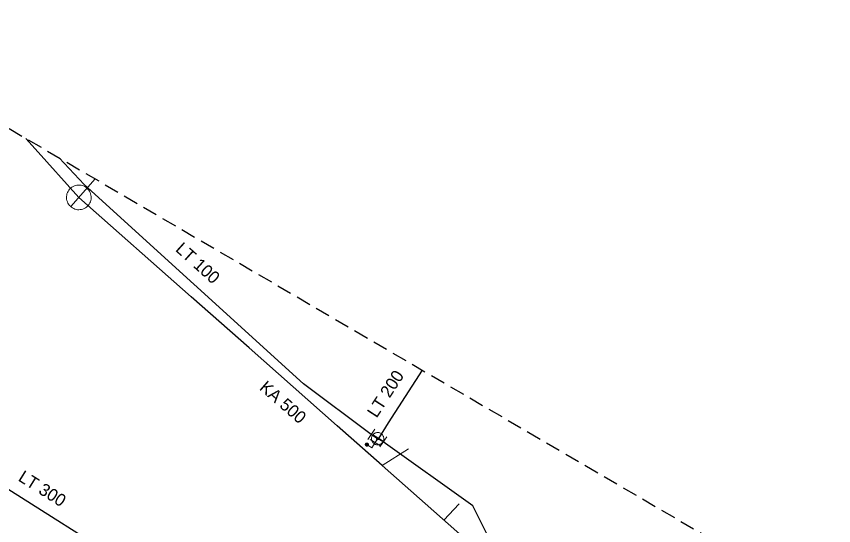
# Model space of a CAD drawing. Extents: x -747112 to -746911, y -964685 to -964545.
# Drawn here: x -747078.9 to -747012.7, y -964586.1 to -964544.9 of the extents above; entities that cross this region are included whole.
import ezdxf

# ---------------------------------------------------------------- set-up
doc = ezdxf.new("R2010")
doc.units = 0
doc.header["$LTSCALE"] = 0.4
doc.linetypes.add('MEDIUM_DASHED', pattern=[4.5, 3, -1.5])
doc.layers.add('1', color=7, linetype='Continuous')
for name, color, linetype, lineweight in [('11', 7, 'Continuous', 13), ('14', 7, 'Continuous', 13), ('17', 7, 'Continuous', 25), ('22', 7, 'Continuous', 13), ('34', 7, 'Continuous', 13), ('47', 7, 'Continuous', 13), ('63', 7, 'MEDIUM_DASHED', 25), ('9', 7, 'Continuous', 13)]:
    doc.layers.add(name, color=color, linetype=linetype, lineweight=lineweight)

msp = doc.modelspace()

# ---------------------------------------------------------------- linework, layer by layer
at = {"layer": '11'}
for p, q in [((-747047.181, -964579.934), (-747049.3, -964581.28)), ((-747043.061, -964584.386), (-747044.313, -964585.69))]:
    msp.add_line(p, q, dxfattribs=at)
at = {"layer": '14'}
for p, q in [((-747049.67, -964579.109), (-747050.182, -964578.759)), ((-747049.67, -964579.109), (-747049.857, -964579.421)), ((-747049.579, -964579.079), (-747049.67, -964579.109)), ((-747049.208, -964579.357), (-747049.67, -964579.109))]:
    msp.add_line(p, q, dxfattribs=at)
at = {"layer": '14', "lineweight": 25}
for points in [[(-747073.861, -964559.579), (-747077.397, -964555.642), (-747078.147, -964554.806)], [(-747037.631, -964591.6), (-747040.938, -964588.675), (-747049.3, -964581.28), (-747052.956, -964578.054), (-747060.077, -964571.761), (-747064.767, -964567.616), (-747073.861, -964559.579)]]:
    msp.add_lwpolyline(points, dxfattribs=at)
at = {"layer": '14'}
msp.add_lwpolyline([(-747049.857, -964579.421), (-747050.124, -964579.837), (-747050.539, -964579.583)], dxfattribs=at)
at = {"layer": '17'}
for points in [[(-747050.182, -964578.759), (-747055.68, -964574.68), (-747073.416, -964558.543), (-747075.451, -964556.382)], [(-747106.776, -964565.501), (-747102.855, -964568.884), (-747090.37, -964576.361), (-747069.903, -964589.309), (-747064.75, -964592.568), (-747063.288, -964593.435)], [(-747049.579, -964579.079), (-747048.793, -964577.816), (-747046.042, -964573.57)], [(-746992.592, -964623.377), (-747002.848, -964615.868), (-747011.265, -964609.743), (-747020.612, -964602.861), (-747030.192, -964595.879), (-747034.92, -964592.421), (-747039.8, -964588.87), (-747041.949, -964584.539), (-747049.208, -964579.357)]]:
    msp.add_lwpolyline(points, dxfattribs=at)
at = {"layer": '22'}
msp.add_line((-747072.536, -964558.079), (-747074.522, -964560.327), dxfattribs=at)
msp.add_lwpolyline([(-747074.609, -964558.916), (-747074.677, -964559.002), (-747074.735, -964559.094), (-747074.783, -964559.194), (-747074.82, -964559.296), (-747074.845, -964559.403), (-747074.858, -964559.511), (-747074.859, -964559.621), (-747074.848, -964559.73), (-747074.826, -964559.838), (-747074.792, -964559.941), (-747074.747, -964560.041), (-747074.69, -964560.135), (-747074.624, -964560.223), (-747074.549, -964560.302), (-747074.466, -964560.374), (-747074.376, -964560.435), (-747074.279, -964560.487), (-747074.177, -964560.527), (-747074.071, -964560.555), (-747073.964, -964560.573), (-747073.854, -964560.578), (-747073.745, -964560.571), (-747073.636, -964560.553), (-747073.531, -964560.523), (-747073.43, -964560.481), (-747073.334, -964560.428), (-747073.244, -964560.365), (-747073.162, -964560.294), (-747073.088, -964560.213), (-747073.023, -964560.124), (-747072.968, -964560.03), (-747072.925, -964559.93), (-747072.891, -964559.826), (-747072.87, -964559.718), (-747072.861, -964559.609), (-747072.863, -964559.5), (-747072.878, -964559.391), (-747072.904, -964559.285), (-747072.942, -964559.182), (-747072.991, -964559.084), (-747073.05, -964558.992), (-747073.119, -964558.907), (-747073.197, -964558.829), (-747073.283, -964558.762), (-747073.376, -964558.704), (-747073.474, -964558.656), (-747073.577, -964558.619), (-747073.684, -964558.594), (-747073.793, -964558.581), (-747073.902, -964558.579), (-747074.011, -964558.589), (-747074.118, -964558.612), (-747074.222, -964558.645), (-747074.322, -964558.691), (-747074.416, -964558.747), (-747074.504, -964558.813), (-747074.584, -964558.888)], close=True, dxfattribs=at)
at = {"layer": '34'}
for p, q in [((-747050.464, -964579.171), (-747049.899, -964578.346)), ((-747050.006, -964578.819), (-747049.152, -964579.339)), ((-747049.428, -964579.679), (-747050.284, -964579.161)), ((-747049.498, -964579.764), (-747048.917, -964578.95))]:
    msp.add_line(p, q, dxfattribs=at)
at = {"layer": '47'}
for points in [[(-747050.11, -964578.872), (-747050.132, -964578.919), (-747050.149, -964578.968), (-747050.161, -964579.019), (-747050.168, -964579.071), (-747050.169, -964579.124), (-747050.165, -964579.176), (-747050.154, -964579.227), (-747050.139, -964579.277), (-747050.12, -964579.325), (-747050.095, -964579.371), (-747050.065, -964579.415), (-747050.03, -964579.454), (-747049.993, -964579.49), (-747049.951, -964579.522), (-747049.906, -964579.549), (-747049.859, -964579.571), (-747049.81, -964579.588), (-747049.758, -964579.6), (-747049.707, -964579.607), (-747049.654, -964579.608), (-747049.602, -964579.604), (-747049.55, -964579.594), (-747049.5, -964579.579), (-747049.452, -964579.559), (-747049.407, -964579.534), (-747049.363, -964579.504), (-747049.323, -964579.47), (-747049.288, -964579.432), (-747049.256, -964579.39), (-747049.229, -964579.345), (-747049.207, -964579.298), (-747049.19, -964579.249), (-747049.177, -964579.198), (-747049.171, -964579.146), (-747049.17, -964579.093), (-747049.174, -964579.041), (-747049.183, -964578.99), (-747049.198, -964578.94), (-747049.219, -964578.891), (-747049.244, -964578.846), (-747049.274, -964578.802), (-747049.307, -964578.763), (-747049.346, -964578.727), (-747049.388, -964578.695), (-747049.433, -964578.668), (-747049.48, -964578.646), (-747049.529, -964578.629), (-747049.58, -964578.616), (-747049.632, -964578.61), (-747049.685, -964578.609), (-747049.737, -964578.613), (-747049.787, -964578.623), (-747049.838, -964578.638), (-747049.886, -964578.658), (-747049.932, -964578.683), (-747049.976, -964578.713), (-747050.014, -964578.747), (-747050.051, -964578.785), (-747050.083, -964578.827)], [(-747049.742, -964579.07), (-747049.746, -964579.078), (-747049.748, -964579.086), (-747049.75, -964579.094), (-747049.751, -964579.102), (-747049.751, -964579.111), (-747049.75, -964579.12), (-747049.749, -964579.128), (-747049.747, -964579.136), (-747049.743, -964579.144), (-747049.739, -964579.152), (-747049.734, -964579.159), (-747049.728, -964579.165), (-747049.722, -964579.171), (-747049.716, -964579.176), (-747049.708, -964579.181), (-747049.7, -964579.185), (-747049.692, -964579.187), (-747049.684, -964579.189), (-747049.676, -964579.19), (-747049.667, -964579.19), (-747049.658, -964579.189), (-747049.65, -964579.188), (-747049.642, -964579.186), (-747049.633, -964579.183), (-747049.626, -964579.178), (-747049.619, -964579.173), (-747049.613, -964579.167), (-747049.607, -964579.161), (-747049.602, -964579.155), (-747049.597, -964579.147), (-747049.593, -964579.139), (-747049.591, -964579.131), (-747049.589, -964579.123), (-747049.588, -964579.115), (-747049.588, -964579.106), (-747049.588, -964579.098), (-747049.59, -964579.089), (-747049.592, -964579.081), (-747049.595, -964579.072), (-747049.6, -964579.065), (-747049.605, -964579.058), (-747049.611, -964579.052), (-747049.617, -964579.046), (-747049.623, -964579.041), (-747049.631, -964579.036), (-747049.639, -964579.032), (-747049.647, -964579.03), (-747049.655, -964579.028), (-747049.663, -964579.027), (-747049.672, -964579.027), (-747049.68, -964579.027), (-747049.689, -964579.029), (-747049.697, -964579.031), (-747049.705, -964579.035), (-747049.713, -964579.039), (-747049.72, -964579.044), (-747049.726, -964579.05), (-747049.732, -964579.056), (-747049.737, -964579.062)]]:
    msp.add_lwpolyline(points, close=True, dxfattribs=at)
at = {"layer": '63'}
msp.add_lwpolyline([(-746919.076, -964684.739), (-747112.263, -964574.928), (-747112.265, -964574.927), (-747112.266, -964574.925), (-747112.267, -964574.924), (-747112.268, -964574.922), (-747112.268, -964574.92), (-747112.268, -964574.918), (-747112.268, -964574.916), (-747112.267, -964574.914), (-747097.677, -964549.903), (-747095.061, -964544.933), (-747095.059, -964544.931), (-747095.058, -964544.93), (-747095.056, -964544.929), (-747095.054, -964544.928), (-747095.052, -964544.928), (-747095.05, -964544.928), (-747095.048, -964544.928), (-747095.047, -964544.929), (-746965.47, -964620.662)], dxfattribs=at)
at = {"layer": '9'}
for points in [[(-747050.665, -964579.583), (-747050.665, -964579.596), (-747050.663, -964579.609), (-747050.66, -964579.622), (-747050.655, -964579.634), (-747050.649, -964579.646), (-747050.642, -964579.657), (-747050.634, -964579.667), (-747050.624, -964579.677), (-747050.614, -964579.685), (-747050.603, -964579.692), (-747050.591, -964579.698), (-747050.579, -964579.703), (-747050.566, -964579.706), (-747050.553, -964579.708), (-747050.54, -964579.71), (-747050.527, -964579.709), (-747050.514, -964579.707), (-747050.501, -964579.704), (-747050.489, -964579.699), (-747050.477, -964579.693), (-747050.466, -964579.686), (-747050.456, -964579.678), (-747050.446, -964579.668), (-747050.438, -964579.658), (-747050.431, -964579.647), (-747050.425, -964579.635), (-747050.42, -964579.623), (-747050.417, -964579.61), (-747050.415, -964579.597), (-747050.413, -964579.584), (-747050.414, -964579.571), (-747050.416, -964579.558), (-747050.419, -964579.545), (-747050.424, -964579.533), (-747050.429, -964579.521), (-747050.437, -964579.51), (-747050.445, -964579.5), (-747050.455, -964579.49), (-747050.465, -964579.482), (-747050.476, -964579.475), (-747050.488, -964579.469), (-747050.5, -964579.464), (-747050.513, -964579.461), (-747050.526, -964579.459), (-747050.539, -964579.458), (-747050.552, -964579.458), (-747050.565, -964579.46), (-747050.578, -964579.463), (-747050.59, -964579.468), (-747050.602, -964579.474), (-747050.613, -964579.481), (-747050.623, -964579.489), (-747050.633, -964579.499), (-747050.641, -964579.509), (-747050.648, -964579.52), (-747050.654, -964579.532), (-747050.659, -964579.544), (-747050.662, -964579.557), (-747050.664, -964579.57)], [(-747050.645, -964579.583), (-747050.646, -964579.594), (-747050.644, -964579.605), (-747050.641, -964579.616), (-747050.637, -964579.626), (-747050.632, -964579.636), (-747050.626, -964579.645), (-747050.619, -964579.654), (-747050.611, -964579.662), (-747050.602, -964579.669), (-747050.593, -964579.675), (-747050.583, -964579.68), (-747050.573, -964579.684), (-747050.562, -964579.687), (-747050.551, -964579.69), (-747050.54, -964579.69), (-747050.529, -964579.69), (-747050.518, -964579.688), (-747050.507, -964579.685), (-747050.497, -964579.681), (-747050.487, -964579.676), (-747050.478, -964579.67), (-747050.469, -964579.663), (-747050.461, -964579.655), (-747050.454, -964579.646), (-747050.448, -964579.637), (-747050.443, -964579.627), (-747050.439, -964579.617), (-747050.436, -964579.606), (-747050.434, -964579.595), (-747050.433, -964579.584), (-747050.433, -964579.573), (-747050.434, -964579.562), (-747050.438, -964579.551), (-747050.442, -964579.541), (-747050.447, -964579.531), (-747050.453, -964579.522), (-747050.46, -964579.513), (-747050.468, -964579.505), (-747050.477, -964579.498), (-747050.486, -964579.492), (-747050.496, -964579.487), (-747050.505, -964579.483), (-747050.517, -964579.48), (-747050.527, -964579.478), (-747050.539, -964579.478), (-747050.55, -964579.477), (-747050.561, -964579.479), (-747050.572, -964579.482), (-747050.581, -964579.486), (-747050.592, -964579.491), (-747050.601, -964579.497), (-747050.61, -964579.504), (-747050.618, -964579.512), (-747050.625, -964579.521), (-747050.63, -964579.53), (-747050.636, -964579.54), (-747050.64, -964579.55), (-747050.643, -964579.561), (-747050.645, -964579.572)], [(-747050.626, -964579.583), (-747050.626, -964579.592), (-747050.625, -964579.601), (-747050.622, -964579.61), (-747050.619, -964579.618), (-747050.615, -964579.626), (-747050.61, -964579.634), (-747050.603, -964579.641), (-747050.598, -964579.647), (-747050.591, -964579.653), (-747050.583, -964579.658), (-747050.575, -964579.662), (-747050.567, -964579.665), (-747050.558, -964579.668), (-747050.549, -964579.669), (-747050.54, -964579.671), (-747050.531, -964579.67), (-747050.522, -964579.669), (-747050.513, -964579.666), (-747050.505, -964579.663), (-747050.497, -964579.659), (-747050.489, -964579.654), (-747050.482, -964579.648), (-747050.476, -964579.642), (-747050.47, -964579.635), (-747050.465, -964579.627), (-747050.461, -964579.619), (-747050.458, -964579.611), (-747050.455, -964579.602), (-747050.454, -964579.593), (-747050.451, -964579.584), (-747050.453, -964579.575), (-747050.454, -964579.566), (-747050.456, -964579.557), (-747050.46, -964579.549), (-747050.464, -964579.541), (-747050.469, -964579.533), (-747050.475, -964579.526), (-747050.481, -964579.52), (-747050.488, -964579.514), (-747050.496, -964579.509), (-747050.504, -964579.505), (-747050.512, -964579.502), (-747050.521, -964579.499), (-747050.53, -964579.498), (-747050.539, -964579.497), (-747050.548, -964579.497), (-747050.557, -964579.498), (-747050.566, -964579.501), (-747050.574, -964579.504), (-747050.581, -964579.508), (-747050.59, -964579.513), (-747050.597, -964579.519), (-747050.603, -964579.525), (-747050.608, -964579.532), (-747050.614, -964579.54), (-747050.618, -964579.548), (-747050.621, -964579.556), (-747050.624, -964579.565), (-747050.625, -964579.574)], [(-747050.606, -964579.583), (-747050.606, -964579.59), (-747050.605, -964579.597), (-747050.603, -964579.604), (-747050.601, -964579.61), (-747050.598, -964579.616), (-747050.594, -964579.622), (-747050.59, -964579.628), (-747050.585, -964579.633), (-747050.579, -964579.637), (-747050.573, -964579.641), (-747050.567, -964579.644), (-747050.561, -964579.647), (-747050.554, -964579.648), (-747050.547, -964579.651), (-747050.54, -964579.651), (-747050.532, -964579.651), (-747050.526, -964579.649), (-747050.519, -964579.648), (-747050.513, -964579.645), (-747050.505, -964579.642), (-747050.501, -964579.638), (-747050.495, -964579.634), (-747050.49, -964579.629), (-747050.486, -964579.623), (-747050.482, -964579.617), (-747050.478, -964579.611), (-747050.476, -964579.605), (-747050.474, -964579.598), (-747050.473, -964579.591), (-747050.472, -964579.584), (-747050.472, -964579.577), (-747050.473, -964579.57), (-747050.475, -964579.563), (-747050.478, -964579.557), (-747050.481, -964579.55), (-747050.485, -964579.545), (-747050.489, -964579.539), (-747050.494, -964579.534), (-747050.5, -964579.53), (-747050.505, -964579.526), (-747050.512, -964579.523), (-747050.518, -964579.52), (-747050.525, -964579.518), (-747050.532, -964579.517), (-747050.539, -964579.517), (-747050.546, -964579.517), (-747050.553, -964579.517), (-747050.559, -964579.519), (-747050.566, -964579.522), (-747050.572, -964579.525), (-747050.578, -964579.529), (-747050.584, -964579.533), (-747050.589, -964579.538), (-747050.593, -964579.544), (-747050.597, -964579.549), (-747050.6, -964579.556), (-747050.603, -964579.562), (-747050.603, -964579.569), (-747050.606, -964579.576)], [(-747050.586, -964579.583), (-747050.586, -964579.588), (-747050.586, -964579.593), (-747050.585, -964579.598), (-747050.583, -964579.602), (-747050.581, -964579.607), (-747050.578, -964579.611), (-747050.575, -964579.614), (-747050.571, -964579.618), (-747050.568, -964579.621), (-747050.564, -964579.624), (-747050.559, -964579.626), (-747050.554, -964579.628), (-747050.55, -964579.629), (-747050.545, -964579.631), (-747050.54, -964579.631), (-747050.535, -964579.631), (-747050.53, -964579.63), (-747050.525, -964579.629), (-747050.521, -964579.627), (-747050.516, -964579.625), (-747050.512, -964579.622), (-747050.508, -964579.619), (-747050.505, -964579.615), (-747050.502, -964579.612), (-747050.499, -964579.608), (-747050.497, -964579.603), (-747050.495, -964579.599), (-747050.494, -964579.594), (-747050.493, -964579.589), (-747050.492, -964579.584), (-747050.492, -964579.579), (-747050.493, -964579.574), (-747050.494, -964579.569), (-747050.496, -964579.565), (-747050.498, -964579.56), (-747050.501, -964579.556), (-747050.504, -964579.552), (-747050.507, -964579.549), (-747050.511, -964579.546), (-747050.515, -964579.543), (-747050.52, -964579.541), (-747050.524, -964579.539), (-747050.529, -964579.538), (-747050.534, -964579.537), (-747050.539, -964579.537), (-747050.544, -964579.537), (-747050.549, -964579.538), (-747050.554, -964579.538), (-747050.558, -964579.54), (-747050.563, -964579.542), (-747050.567, -964579.545), (-747050.57, -964579.548), (-747050.574, -964579.551), (-747050.576, -964579.555), (-747050.58, -964579.559), (-747050.581, -964579.564), (-747050.584, -964579.568), (-747050.585, -964579.573), (-747050.586, -964579.578)], [(-747050.566, -964579.583), (-747050.566, -964579.586), (-747050.567, -964579.589), (-747050.566, -964579.591), (-747050.565, -964579.594), (-747050.564, -964579.597), (-747050.562, -964579.599), (-747050.559, -964579.601), (-747050.558, -964579.603), (-747050.556, -964579.605), (-747050.554, -964579.607), (-747050.551, -964579.609), (-747050.548, -964579.61), (-747050.546, -964579.61), (-747050.543, -964579.611), (-747050.54, -964579.611), (-747050.537, -964579.611), (-747050.534, -964579.611), (-747050.531, -964579.61), (-747050.529, -964579.609), (-747050.526, -964579.608), (-747050.524, -964579.606), (-747050.521, -964579.604), (-747050.519, -964579.602), (-747050.518, -964579.6), (-747050.516, -964579.598), (-747050.515, -964579.595), (-747050.513, -964579.592), (-747050.513, -964579.59), (-747050.512, -964579.587), (-747050.511, -964579.584), (-747050.512, -964579.581), (-747050.512, -964579.578), (-747050.513, -964579.575), (-747050.514, -964579.573), (-747050.515, -964579.57), (-747050.517, -964579.568), (-747050.518, -964579.565), (-747050.52, -964579.563), (-747050.523, -964579.562), (-747050.525, -964579.56), (-747050.527, -964579.559), (-747050.53, -964579.558), (-747050.532, -964579.557), (-747050.536, -964579.557), (-747050.539, -964579.556), (-747050.542, -964579.557), (-747050.545, -964579.556), (-747050.547, -964579.558), (-747050.55, -964579.558), (-747050.553, -964579.559), (-747050.554, -964579.561), (-747050.557, -964579.562), (-747050.559, -964579.564), (-747050.561, -964579.567), (-747050.563, -964579.569), (-747050.564, -964579.572), (-747050.565, -964579.574), (-747050.566, -964579.577), (-747050.566, -964579.58)], [(-747050.547, -964579.583), (-747050.547, -964579.585), (-747050.547, -964579.585), (-747050.546, -964579.585), (-747050.546, -964579.587), (-747050.547, -964579.588), (-747050.545, -964579.588), (-747050.545, -964579.588), (-747050.545, -964579.59), (-747050.545, -964579.59), (-747050.544, -964579.591), (-747050.542, -964579.591), (-747050.542, -964579.591), (-747050.542, -964579.592), (-747050.54, -964579.592), (-747050.54, -964579.592), (-747050.539, -964579.592), (-747050.538, -964579.592), (-747050.538, -964579.591), (-747050.537, -964579.591), (-747050.535, -964579.591), (-747050.535, -964579.59), (-747050.535, -964579.59), (-747050.534, -964579.589), (-747050.534, -964579.589), (-747050.532, -964579.588), (-747050.532, -964579.587), (-747050.531, -964579.586), (-747050.531, -964579.586), (-747050.531, -964579.585), (-747050.531, -964579.584), (-747050.531, -964579.583), (-747050.531, -964579.582), (-747050.531, -964579.582), (-747050.532, -964579.581), (-747050.532, -964579.58), (-747050.532, -964579.579), (-747050.532, -964579.579), (-747050.534, -964579.578), (-747050.534, -964579.578), (-747050.535, -964579.577), (-747050.536, -964579.577), (-747050.537, -964579.576), (-747050.537, -964579.576), (-747050.538, -964579.576), (-747050.539, -964579.576), (-747050.54, -964579.576), (-747050.541, -964579.576), (-747050.541, -964579.576), (-747050.542, -964579.577), (-747050.543, -964579.576), (-747050.544, -964579.578), (-747050.544, -964579.578), (-747050.545, -964579.578), (-747050.545, -964579.578), (-747050.546, -964579.58), (-747050.546, -964579.581), (-747050.546, -964579.582), (-747050.547, -964579.582), (-747050.547, -964579.583)]]:
    msp.add_lwpolyline(points, close=True, dxfattribs=at)

# ---------------------------------------------------------------- texts
at = {"layer": '1'}
for s, rotation, p in [('LT 100', 318, (-747066.104, -964563.864)), ('LT 200', 57, (-747049.749, -964577.488)), ('KA 500', 319, (-747059.308, -964575.089)), ('LT 300', 328, (-747078.841, -964582.463))]:
    msp.add_text(s, height=1, rotation=rotation, dxfattribs=at).set_placement(p)

doc.saveas('drawing.dxf')
